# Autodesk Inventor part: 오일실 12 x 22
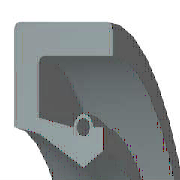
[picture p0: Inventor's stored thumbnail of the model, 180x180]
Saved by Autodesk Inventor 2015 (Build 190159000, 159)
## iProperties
IsCustomPart: 0
Created: 2015-10
Part Number: 오일실 12 x 22
Material: 고무
Description: 오일-실
Document SubType Name: Modeling
Standard: KS B 2804
Designer: mdu
Standards Organization: KS
Language: ko-KR
Size Designation: S - 12 22 7
Categories: <MemberInstance><Categories><Category DisplayName="샤프트 부품" InternalName="7f7aeb1f-a693-4053-b835-cee3144e0d98" Mnemonic="SHFT"><Category DisplayName="실링" Intern
Density: 0.93 g/cm^3
Appearance: 고무 - 검은색 - 버전 1.1
Mass: 1.0258 g
Surface Area: 17.5559 cm^2
Volume: 1.10301 cm^3
Author: mdu
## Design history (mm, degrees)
revolve "본체" stored, may be unused: angle "d17" = 90 deg
revolve "스프링1" stored, may be unused: angle "d18" = 90 deg
body "Solid1"
sketch "스케치1"
  geometry: L1 (0, 11)-(7, 11); L2 (7, 11)-(7, 9.75); L3 (7, 9.75)-(1.75, 9.75); L4 (0, 11)-(0, 8.1); L5 (0, 8.1)-(1.75, 7.75); L6 (1.75, 7.75)-(4.9, 6); L7 (4.9, 6)-(0, 6); L8 (6.3, 6.875)-(6.3, 8.1); L9 (0, 0)-(9.586, 0) reference; L10 (4.9, 6)-(6.3, 6.875); L11 (0, 18)-(0, -3) reference; L12 (-1.917, 0)-(11.503, 0) reference; L13 (4.2, 8.1)-(1.75, 8.59); L14 (1.75, 8.59)-(1.75, 9.75); L15 (6.3, 8.1)-(5.6, 8.1); C1 r 0.455 at (4.9, 8.1); A1 r 0.7 centre (4.9, 8.1) between (5.6, 8.1) and (4.2, 8.1)
  constraints: 26 end point, 5 horizontal alignment, 4 perpendicular, 2 centre point, 2 collinear, 2 horizontal, 2 parallel, 2 point on circle, 2 point on line, 2 vertical alignment, 1 coincident
  dimensions: "d0" = 22 diameter of L1 L9 (= SD2); "d1" = 13.75 diameter of L8.start L9 (= ABDM); "d2" = 1.25 distance of L1.end L2.end (computed from SD); "d3" = 0.91 diameter of C1 (= SPDI); "d4" = 1.4 diameter of A1 (= SPDA); "d5" = 12 diameter of L6.end L9 (= NND); "d6" = 15.5 diameter of L5.end L9 (= TKDM); "d7" = 16.2 diameter of L4.end L9 (= HLDM); "d8" = 4.9 distance from line of C1.centre L4 (= SPDST); "d9" = 6.3 distance between parallel lines of L8 L4 (= SDI); "d10" = 7 distance between parallel lines of L2 L4 (= SWDT); "d12" = 1.75 distance between parallel lines of L14 L4 (= SD)
fillet "모깎기1" dims "d11" = 0.3 (= RR)
other parameters: "SD2" = 22 [user parameter; used in 1 equation term], "SWDT" = 7 [user parameter; used in 1 equation term], "RR" = 0.3 [user parameter; used in 1 equation term], "SD" = 1.75 [user parameter; used in 2 equation terms], "NND" = 12 [user parameter; used in 1 equation term], "SPDA" = 1.4 [user parameter; used in 1 equation term], "SPDI" = 0.91 [user parameter; used in 1 equation term], "TKDM" = 15.5 [user parameter; used in 1 equation term], "HLDM" = 16.2 [user parameter; used in 1 equation term], "ABDM" = 13.75 [user parameter; used in 1 equation term], "SDI" = 6.3 [user parameter; used in 1 equation term], "SPDST" = 4.9 [user parameter; used in 1 equation term], "d13" = 0, "d14" = 0, "d15" = 0, "LAB" = 0.35 [user parameter]
